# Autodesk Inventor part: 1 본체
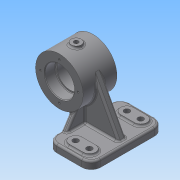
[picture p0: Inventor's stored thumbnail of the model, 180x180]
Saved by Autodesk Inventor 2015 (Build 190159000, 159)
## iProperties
Created: 2023-08
Part Number: 1 본체
Material: 일반
Document SubType Name: Modeling
Designer: 학생용
Density: 1 g/cm^3
Appearance: 기본값
Author: 학생용
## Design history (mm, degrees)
sketch "스케치1"
  geometry: L1 (35, 58)-(-35, 58); L2 (-35, 58)-(-35, -58); L3 (-35, -58)-(35, -58); L4 (35, -58)-(35, 58); L5 (35, 58)-(-35, -58); L6 (-35, 58)-(35, -58); 1 further point
  constraints: 12 end point, 2 midpoint, 2 parallel, 1 horizontal, 1 perpendicular
  dimensions: "d0" = 70 distance of L2.end L3.end; "d1" = 116 distance of L1.end L2.end
extrude "돌출1" new body sketch "스케치1" stored distance "d2" = 12; taper "d3" = 0 deg
sketch "스케치2"
  geometry: L1 (-17, -41)-(25, -41); L2 (-7, -31)-(15, -31); L3 (15, -51)-(-7, -51); L4 (35, -58)-(35, 58) reference; A1 r 10 centre (-7, -41) between (-7, -31) and (-7, -51); A2 r 10 centre (15, -41) between (15, -51) and (15, -31); 2 further points
  constraints: 8 end point, 6 point on circle, 4 tangent, 2 centre point, 2 point on line, 1 horizontal, 1 midpoint, 1 parallel
  dimensions: "d4" = 20 distance between parallel lines of L3 L2; "d6" = 41 vertical distance of point (0, 0) point (4, -41); "d7" = 22 distance of A1.centre A2.centre; "d19" = 20 distance from line of L4 A2.centre
extrude "돌출2" join sketch "스케치2" distance "d8" = 3; taper "d9" = 0 deg
sketch "스케치3"
  geometry: C1 r 4.5 at (15, -41); C2 r 4.5 at (-7, -41); A1 r 10 centre (15, -41) between (15, -51) and (15, -31) reference; A2 r 10 centre (-7, -41) between (-7, -31) and (-7, -51) reference; 1 further point
  constraints: 2 centre point, 2 coincident
  dimensions: "d10" = 9 diameter of C2; "d11" = 9 diameter of C1
extrude "돌출3" cut sketch "스케치3" stored distance "d12" = 3; taper "d13" = 0 deg
sketch "스케치4"
  geometry: L1 (-35, -6)-(35, -6) reference; L2 (-11.5, 9)-(-2.5, 9) reference; L3 (-7, 6)-(-7, 9) reference; L4 (-11.5, 9)-(-2.5, 9) reference; L5 (10.5, 9)-(19.5, 9) reference; C1 r 38 at (-47, 64); 1 further point
  constraints: 1 centre point
  dimensions: "d21" = 76 diameter of C1; "d22" = 40 distance from line of L3 C1.centre; "d23" = 70 distance from line of L1 C1.centre
extrude "돌출4" join sketch "스케치4" stored distance "d17" = 54; taper "d18" = 0 deg
sketch "스케치5"
  geometry: L1 (-116, 12)-(0, 12) reference; L2 (-94, 12)-(-68.462, 51.325); L3 (-47.538, 51.325)-(-22, 12); L4 (0, 12)-(0, 0) reference; L5 (-116, 0)-(-116, 12) reference; L6 (-94, 12)-(-22, 12); L7 (-27, 12)-(-7, 12) reference; L8 (-68.462, 51.325)-(-47.538, 51.325); 1 further point
  constraints: 8 end point, 2 point on line, 1 collinear, 1 horizontal
  dimensions: "d24" = 22 distance from line of L4 L3.end; "d25" = 22 distance from line of L5 L2.start; "d26" = 33 deg angle of L5 L2; "d27" = 33 deg angle of L4 L3; "d31" = 39.32489 distance between parallel lines of L1 L8
extrude "돌출5" join sketch "스케치5" distance "d29" = 8; taper "d30" = 0 deg
sketch "스케치6"
  geometry: C1 r 38 at (0, 0) reference; C2 r 23.5 at (0, 0); 1 further point
  constraints: 1 centre point, 1 coincident
  dimensions: "d32" = 47 diameter of C2
extrude "돌출6" cut sketch "스케치6" distance "d33" = 17; taper "d34" = 0 deg
sketch "스케치7"
  geometry: C1 r 38 at (0, 0) reference; C2 r 23.5 at (0, 0); 1 further point
  constraints: 1 centre point, 1 coincident
  dimensions: "d35" = 47 diameter of C2
extrude "돌출7" cut sketch "스케치7" distance "d36" = 17; taper "d37" = 0 deg
sketch "스케치8"
  geometry: C1 r 23.5 at (0, 0) reference; C2 r 20.5 at (0, 0); 1 further point
  constraints: 1 centre point, 1 coincident
  dimensions: "d38" = 41 diameter of C2
extrude "돌출8" cut sketch "스케치8" stored distance "d39" = 17; taper "d40" = 0 deg
sketch "스케치9"
  geometry: L1 (0, 0)-(-116, 0) reference; 2 further points
  constraints: 1 vertical alignment, 1 other
  dimensions: "d41" = 19 distance from line of L1 point (-58, 19)
feature "엠보싱1" sketch "스케치9" dims "d0" = 70, "d1" = 116, "d42" = 0.5, "d43" = 0
sketch "스케치10" dims "d44" = 60
  geometry: C1 r 38 at (0, 0) reference; 3 further points
  constraints: 2 vertical alignment, 1 coincident, 2 other
hole "구멍1" sketch "스케치10" at (0, 30) diameter "d45" = 3.242; stored, may be unused: countersink angle "d49" = 82 deg, drill point angle "d51" = 118 deg; dims "d46" = 8, "d47" = 3.023, "d48" = 2, "d50" = 10
node "작업 평면2"
node "작업 평면5"
  node "작업 평면3"
  node "작업 평면4"
node "작업 평면6"
sketch "스케치11"
  geometry: L1 (-35, -21.749)-(-35, 21.749) reference; L2 (-27, 19.317)-(-27, -19.317) reference; L3 (-85, -27)-(-9, -27) reference; L4 (-9, 27)-(-85, 27) reference; C1 r 8 at (-47, 0); 4 further points; 2 other entities
  constraints: 1 centre point, 1 midpoint, 1 vertical alignment, 2 other
  dimensions: "d56" = 16 diameter of C1
extrude "돌출9" join sketch "스케치11" stored distance "d57" = 0; taper "d58" = 0 deg
sketch "스케치12"
  geometry: C1 r 8 at (0, 0) reference; 2 further points
  constraints: 1 coincident
hole "구멍2" sketch "스케치12" at (0, 0) diameter "d59" = 5.188; stored, may be unused: countersink angle "d63" = 82 deg, drill point angle "d65" = 118 deg; dims "d60" = 40, "d61" = 7, "d62" = 4, "d64" = 41
sketch "스케치13"
  geometry: L1 (-13.471, 81.882)-(27, 6); L2 (35, 6)-(-35, 6) reference; L3 (35, -6)-(35, 6) reference; 2 further points
  constraints: 2 end point, 1 point on line, 3 other
  dimensions: "d66" = 8 distance from line of L3 L1.end
feature "리브1" sketch "스케치13" dims "d67" = 1, "d68" = 12, "d69" = 0, "d70" = 0, "d71" = 1, "d72" = 1
fillet "모깎기1" dims "d73" = 1
chamfer "모따기1" distance "d74" = 1; stored, may be unused: second distance "d75" = 2, angle "d76" = 45 deg
fillet "모깎기2" dims "d77" = 3
fillet "모깎기3" dims "d78" = 15
fillet "모깎기4" dims "d79" = 3
fillet "모깎기5" dims "d80" = 3
fillet "모깎기6" dims "d81" = 3
fillet "모깎기7" dims "d82" = 3
fillet "모깎기8" dims "d83" = 3
node "솔리드1"
mirror "대칭1"
pattern_circular "원형 패턴1" dims angle "d53" = 360 deg
mirror "대칭2"
node "작업 평면1"
node "투영된 루프1"
other parameters: "d55" = -111
